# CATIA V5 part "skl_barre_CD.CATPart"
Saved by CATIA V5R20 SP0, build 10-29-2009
Part number: skl_barre_CD
Publications: "Axe_pivot_CD_C", "Droite_CD", "Axe_pivot_CD_D"
Bounding box of the stored display mesh (mm): x -5 to 0, y 19 to 131, z 144.003 to 205.997
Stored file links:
  D:\Dropbox\IAO_2012\IAO_2012_742_prousseau\skl_barre_CD.CATPart
  D:\Dropbox\IAO_2012\IAO_2012_742_prousseau\skl_IAO.CATProduct
  D:\Dropbox\IAO_2012\IAO_2012_742_prousseau\skl_barre_BC.CATPart
  D:\Dropbox\IAO_2012\IAO_2012_742_prousseau\skl_barre_FC.CATPart
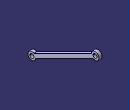
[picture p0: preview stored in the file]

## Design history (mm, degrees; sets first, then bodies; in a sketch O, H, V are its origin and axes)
Set1
  Point1 "Point_C": linked copy from another document
Set2
  Line1 "Droite_CD": type PtPt, FirstPoint Point2, SecondPoint Point3
  Point2 "Point_C": stored without definition
  Point3 "Point_D": stored without definition
  Line2 "Axe_pivot_CD_C": type Normal, RefPoint Point2, RefSkin Plane1, Start -20, End 20
  Plane1 "Plan_Ref": stored without definition
  Line3 "Axe_pivot_CD_D": type Normal, RefPoint Point3, RefSkin Plane1, Start -20, End 20
Body1 (main body)
  Sketch1 on yz-plane, origin (0, 0, 0), H (0, 1, 0), V (0, 0, 1)
    line L1 (28.3059, 155.0071) -> (119.0108, 200.3595)
    line L2 (121.6941, 194.9929) -> (30.9892, 149.6405)
    reference projected line E1 (25, 150) -> (125, 200) from Line1
    reference projected line E2 (25, 150) -> (125, 200) from Line1
    arc A1 centre (25, 150) radius 6 from (28.3059, 155.0071) to (30.9892, 149.6405) ccw
    point P1 (25, 150)
    circle A2 centre (25, 150) radius 3
    point P2 (25, 150)
    circle A3 centre (125, 200) radius 3
    point P3 (125, 200)
    arc A4 centre (125, 200) radius 6 from (121.6941, 194.9929) to (119.0108, 200.3595) ccw
    point P4 (125, 200)
    reference projected point E3 (125, 200) from Point3
    reference projected point E4 (25, 150) from Point1
    reference projected point E5 (25, 150) from Point1
    distance L2 L1 = 6
    radius A2 = 3
    radius A1 = 6
    radius A3 = 3
    radius A4 = 6
    parallelism: L2 E1
    symmetry: L1 L2 E2
    coincidence: P4 E3, P3 P4, P2 E4, P1 E5
  Pad1: profile Sketch1, direction (-1, 0, 0), length 5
